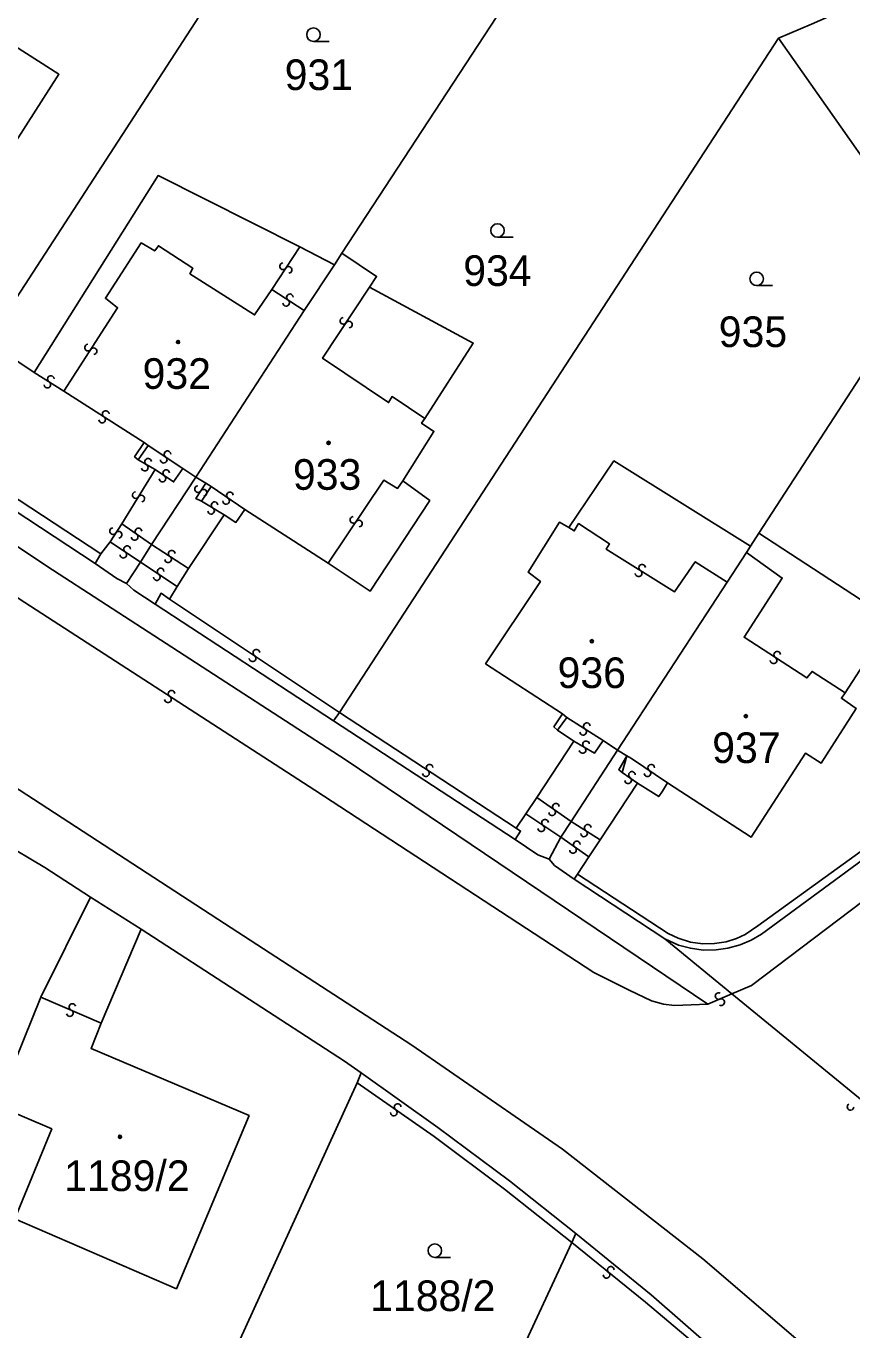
# Model space of a CAD drawing. Extents: x -600309 to -598967, y -1161267 to -1160292.
# Drawn here: x -600003.6 to -599957.8, y -1160420.2 to -1160347.8 of the extents above; entities that cross this region are included whole.
import ezdxf

# ---------------------------------------------------------------- set-up
doc = ezdxf.new("R2010")
doc.units = 0
for name, color, linetype in [('Level 1', 7, 'Continuous'), ('Level 13', 7, 'Continuous'), ('Level 3', 7, 'Continuous'), ('Level 4', 7, 'Continuous'), ('Level 5', 7, 'Continuous'), ('Level 60', 7, 'Continuous'), ('Vrstva 60', 7, 'Continuous')]:
    doc.layers.add(name, color=color, linetype=linetype)

msp = doc.modelspace()

# ---------------------------------------------------------------- linework, layer by layer
at = {"layer": 'Level 1'}
for points in [[(-599985.02, -1160333.4), (-600005.73, -1160365.35)], [(-599973.4, -1160341.02), (-599986.11, -1160360.44)], [(-600013.04, -1160343.31), (-600001.8, -1160350.51), (-600009.56, -1160362.64), (-600010.82, -1160361.78), (-600013.59, -1160366.12)], [(-599960.06, -1160347.74), (-599961.88, -1160348.52)], [(-599961.88, -1160348.52), (-599986.23, -1160385.92)], [(-599961.88, -1160348.52), (-599953.18, -1160360.9)], [(-599988.44, -1160360.09), (-599996.3, -1160356.14), (-600003.16, -1160367.07)], [(-599986.52, -1160361.09), (-599988.44, -1160360.09)], [(-599986.11, -1160360.44), (-599986.52, -1160361.09)], [(-599986.11, -1160360.44), (-599984.18, -1160361.73), (-599984.57, -1160362.32)], [(-599986.52, -1160361.09), (-599988.2, -1160363.63)], [(-599953.18, -1160360.9), (-599962.98, -1160375.98)], [(-599984.57, -1160362.32), (-599978.82, -1160365.43), (-599981.51, -1160369.61)], [(-599988.2, -1160363.63), (-599994.2, -1160372.87)], [(-600003.16, -1160367.07), (-600005.73, -1160365.35)], [(-599981.51, -1160369.61), (-599981.68, -1160369.88), (-599981, -1160370.33), (-599982.73, -1160373.08)], [(-599999.78, -1160377.66), (-600009.6, -1160371.2)], [(-599963.44, -1160376.7), (-599971.02, -1160371.97), (-599973.51, -1160375.67)], [(-599994.2, -1160372.87), (-599996.66, -1160376.6)], [(-599982.73, -1160373.08), (-599981.23, -1160374.17), (-599984.54, -1160379.2), (-599986.86, -1160377.65)], [(-599992.64, -1160374.96), (-599994.61, -1160377.94)], [(-599991.48, -1160374.67), (-599991.98, -1160375.38), (-599992.64, -1160374.96)], [(-599986.86, -1160377.65), (-599991.48, -1160374.67)], [(-599973.51, -1160375.67), (-599974.04, -1160375.37), (-599975.78, -1160378.14), (-599975.09, -1160378.65), (-599978.13, -1160383.22), (-599973.86, -1160386)], [(-599962.98, -1160375.98), (-599963.44, -1160376.7)], [(-599962.98, -1160375.98), (-599955.58, -1160380.8), (-599958.2, -1160384.83)], [(-599996.66, -1160376.6), (-599997.28, -1160377.58)], [(-599963.67, -1160377.05), (-599964.74, -1160378.7)], [(-599963.44, -1160376.7), (-599963.67, -1160377.05)], [(-599998.05, -1160378.77), (-599998.58, -1160378.49), (-599999.78, -1160377.66)], [(-599997.28, -1160377.58), (-599998.05, -1160378.77)], [(-599994.61, -1160377.94), (-599995.23, -1160378.94)], [(-599996.45, -1160379.91), (-599997.65, -1160379.13), (-599998.05, -1160378.77)], [(-599995.67, -1160379.63), (-599996.13, -1160379.31), (-599996.45, -1160379.91)], [(-599995.23, -1160378.94), (-599995.67, -1160379.63)], [(-599964.74, -1160378.7), (-599970.81, -1160388.01)], [(-599986.57, -1160386.39), (-599996.45, -1160379.91)], [(-599941.94, -1160383.8), (-599947.99, -1160387.75), (-599955.91, -1160393.14), (-599962.84, -1160398.22), (-599963.41, -1160398.56), (-599964.02, -1160398.82), (-599964.69, -1160399.01), (-599965.35, -1160399.1), (-599966.07, -1160399.11), (-599966.77, -1160399.01), (-599967.44, -1160398.83), (-599968.2, -1160398.49)], [(-599958.2, -1160384.83), (-599958.4, -1160385.14), (-599957.58, -1160385.71), (-599959.52, -1160388.73), (-599960.4, -1160388.19), (-599963.41, -1160392.85), (-599968.05, -1160389.83)], [(-599986.23, -1160385.92), (-599986.57, -1160386.39)], [(-599976.5, -1160392.98), (-599986.57, -1160386.39)], [(-599973.86, -1160386), (-599974.34, -1160386.72), (-599974.14, -1160386.91)], [(-599974.14, -1160386.91), (-599973.23, -1160387.51)], [(-599973.23, -1160387.51), (-599975.3, -1160390.65)], [(-599970.81, -1160388.01), (-599973.38, -1160391.97)], [(-599969.7, -1160389.84), (-599971.77, -1160393)], [(-599968.05, -1160389.83), (-599968.32, -1160390.3), (-599968.53, -1160390.59), (-599969.7, -1160389.84)], [(-599975.3, -1160390.65), (-599975.91, -1160391.55)], [(-599975.91, -1160391.55), (-599976.44, -1160392.35)], [(-599976.44, -1160392.35), (-599976.19, -1160392.51), (-599976.5, -1160392.98)], [(-599973.38, -1160391.97), (-599973.96, -1160392.85)], [(-600005, -1160393.09), (-600002.57, -1160394.53), (-600000.04, -1160396.18)], [(-599974.61, -1160394.06), (-599975.24, -1160393.82), (-599976.5, -1160392.98)], [(-599973.96, -1160392.85), (-599974.61, -1160394.06)], [(-599971.77, -1160393), (-599972.4, -1160393.94)], [(-599973.22, -1160395.17), (-599974.31, -1160394.42), (-599974.61, -1160394.06)], [(-599972.4, -1160393.94), (-599973.03, -1160394.89)], [(-599973.03, -1160394.89), (-599973.22, -1160395.17)], [(-599968.2, -1160398.49), (-599973.22, -1160395.17)], [(-600000.04, -1160396.18), (-600002.79, -1160401.73)], [(-600000.04, -1160396.18), (-599997.23, -1160397.94)], [(-599999.45, -1160403.16), (-599997.23, -1160397.94)], [(-599997.23, -1160397.94), (-599985.95, -1160405.27), (-599985.04, -1160405.92)], [(-599968.2, -1160398.49), (-599964.48, -1160401.54)], [(-600002.79, -1160401.73), (-600005.24, -1160407.73), (-600002.19, -1160409.03), (-600004.24, -1160414.02), (-599995.28, -1160417.9), (-599991.25, -1160408.29), (-600000.01, -1160404.57), (-599999.45, -1160403.16)], [(-599964.48, -1160401.54), (-599957.66, -1160407.13)], [(-599985.25, -1160406.48), (-599985.04, -1160405.92)], [(-599985.04, -1160405.92), (-599980.78, -1160408.96), (-599976.81, -1160411.91), (-599973.13, -1160414.83)], [(-599993.87, -1160425.35), (-599985.25, -1160406.48)], [(-599973.13, -1160414.83), (-599973.35, -1160415.33)], [(-599973.13, -1160414.83), (-599968.95, -1160418.24), (-599965.44, -1160421.3), (-599961.56, -1160424.77)], [(-599973.35, -1160415.33), (-599978.05, -1160425.46)]]:
    msp.add_lwpolyline(points, dxfattribs=at)
at = {"layer": 'Level 13'}
for centre, start, end in [((-599989.364, -1160361.168), 94.35736, 326.45536), ((-599989.056, -1160361.371), 274.14291, 146.73291), ((-599988.987, -1160362.887), 4.05568, 236.15368), ((-599989.192, -1160363.193), 183.84123, 56.43123), ((-599986.023, -1160364.198), 93.80425, 326.39425), ((-599985.717, -1160364.403), 274.01871, 146.11671), ((-600000.184, -1160365.679), 94.54984, 326.64784), ((-599999.876, -1160365.88), 274.33539, 146.92539), ((-600002.438, -1160367.736), 185.27868, 57.86868), ((-600002.241, -1160367.424), 5.49314, 237.59113), ((-599999.2, -1160369.365), 4.52077, 237.11077), ((-599999.401, -1160369.674), 184.73523, 56.83322), ((-599995.777, -1160371.598), 3.32998, 235.91998), ((-599996.847, -1160372.02), 7.75792, 239.85592), ((-599995.984, -1160371.902), 183.54444, 55.64244), ((-599997.032, -1160372.34), 187.54347, 60.13347), ((-599996.053, -1160372.943), 183.46821, 56.05821), ((-599995.846, -1160372.637), 3.68267, 235.78066), ((-599994.085, -1160373.53), 94.55794, 327.14794), ((-599993.776, -1160373.731), 274.7724, 146.8704), ((-599997.536, -1160373.863), 95.58265, 328.17265), ((-599997.224, -1160374.058), 275.7971, 147.8951), ((-599993.162, -1160374.424), 5.86847, 237.96646), ((-599992.525, -1160374.181), 182.76695, 55.35695), ((-599992.314, -1160373.879), 2.98141, 235.0794), ((-599993.357, -1160374.737), 185.65401, 58.24401), ((-599998.794, -1160375.859), 94.13441, 326.72441), ((-599997.384, -1160375.879), 2.73179, 234.82978), ((-599985.463, -1160375.237), 93.38244, 325.97244), ((-599985.158, -1160375.444), 273.59689, 145.69489), ((-599998.486, -1160376.062), 274.34887, 146.44686), ((-599997.595, -1160376.181), 182.51733, 55.10733), ((-599998.223, -1160377.173), 183.46821, 56.05821), ((-599998.016, -1160376.867), 3.68267, 235.78066), ((-599995.538, -1160377.117), 4.20175, 236.29975), ((-599996.157, -1160378.107), 3.81186, 235.90985), ((-599995.741, -1160377.424), 183.9873, 56.5773), ((-599969.45, -1160377.895), 5.177, 237.275), ((-599996.362, -1160378.413), 183.5974, 56.1874), ((-599969.649, -1160378.205), 184.96254, 57.55254), ((-599991.053, -1160382.923), 183.48222, 56.07222), ((-599990.846, -1160382.617), 3.69668, 235.79467), ((-599962.161, -1160383.034), 184.23262, 56.82262), ((-599961.958, -1160382.726), 4.44708, 236.54507), ((-599995.752, -1160385.194), 184.45419, 56.55219), ((-599995.549, -1160384.886), 4.23974, 236.82974), ((-599972.519, -1160386.686), 4.75349, 236.85149), ((-599972.72, -1160386.995), 184.53904, 57.12904), ((-599972.756, -1160388.007), 186.12001, 58.71001), ((-599972.563, -1160387.693), 6.33447, 238.43247), ((-599981.442, -1160389.293), 183.86166, 56.45166), ((-599981.237, -1160388.987), 4.07612, 236.17412), ((-599970.013, -1160389.389), 2.60754, 234.70553), ((-599969.154, -1160389.302), 182.94258, 55.53258), ((-599968.945, -1160388.998), 3.15703, 235.25503), ((-599970.226, -1160389.691), 182.39308, 54.98308), ((-599974.445, -1160391.461), 182.64976, 55.23976), ((-599974.234, -1160391.159), 2.86421, 234.96221), ((-599975.043, -1160392.353), 183.46821, 56.05821), ((-599974.836, -1160392.047), 3.68267, 235.78066), ((-599972.469, -1160392.326), 4.76359, 236.86159), ((-599973.073, -1160393.25), 2.43004, 234.52804), ((-599972.67, -1160392.635), 184.54913, 57.13913), ((-599973.286, -1160393.55), 182.21559, 54.80559), ((-599965.212, -1160401.661), 60.35687, 292.94687), ((-599965.069, -1160402), 240.57133, 112.66932), ((-600001.193, -1160402.609), 193.98039, 66.57039), ((-600001.046, -1160402.271), 14.19485, 246.29285), ((-599983.226, -1160408.12), 182.18431, 54.77431), ((-599983.013, -1160407.82), 2.39877, 234.49677), ((-599957.894, -1160407.806), 122.98351, 355.57351), ((-599971.427, -1160417.132), 178.10674, 50.69674), ((-599971.192, -1160416.848), 358.32119, 230.41919)]:
    msp.add_arc(centre, 0.184, start, end, dxfattribs=at)
at = {"layer": 'Level 3'}
for points in [[(-600028.67, -1160360.31), (-600002.46, -1160377.81), (-599985.92, -1160388.53), (-599965.81, -1160402.11)], [(-600001.52, -1160368.09), (-599998.54, -1160363.47), (-599999.22, -1160362.94), (-599997.24, -1160359.87), (-599996.48, -1160360.32), (-599996.28, -1160360.03), (-599994.36, -1160361.28), (-599994.53, -1160361.58), (-599990.94, -1160363.87), (-599989.98, -1160362.46)], [(-599989.98, -1160362.46), (-599988.44, -1160360.09)], [(-599899.14, -1160360.13), (-599900.24, -1160362.89), (-599919.3, -1160372.78), (-599932.71, -1160380.45), (-599942.21, -1160386.33), (-599950.05, -1160391.5), (-599957.16, -1160396.36), (-599963.39, -1160401.08), (-599964.48, -1160401.54)], [(-599912.7, -1160482.51), (-599912.12, -1160481.96), (-599911.66, -1160481.24), (-599911.44, -1160480.44), (-599911.45, -1160479.4), (-599911.76, -1160478.46), (-599912.23, -1160477.79), (-599914.13, -1160474.8), (-599932.72, -1160449.47), (-599939, -1160442.13), (-599955.49, -1160425.33), (-599966.09, -1160416.24), (-599973.86, -1160410.16), (-599982.22, -1160404.39), (-599992.61, -1160397.63), (-600009.1, -1160386.91), (-600023.99, -1160377.27), (-600035.97, -1160369.05), (-600043.73, -1160362.3), (-600044.47, -1160362.08), (-600045.32, -1160361.98), (-600046.31, -1160362.05), (-600047.41, -1160362.36), (-600048.26, -1160362.83)], [(-599965.81, -1160402.11), (-599966.73, -1160402.15), (-599967.65, -1160402.19), (-599968.27, -1160402.11), (-599968.94, -1160401.92), (-599970.17, -1160401.33), (-599972.13, -1160400.36), (-599987.61, -1160390.24), (-600003.69, -1160379.83), (-600018.92, -1160369.76), (-600030, -1160362.06)], [(-599989.98, -1160362.46), (-599988.2, -1160363.63)], [(-599984.57, -1160362.32), (-599987.17, -1160366.27), (-599983.51, -1160368.73), (-599983.32, -1160368.4), (-599981.51, -1160369.61)], [(-600003.16, -1160367.07), (-600001.52, -1160368.09)], [(-599997.07, -1160370.94), (-600001.52, -1160368.09)], [(-600009.25, -1160370.71), (-599999.47, -1160377.12)], [(-599997.07, -1160370.94), (-599997.6, -1160371.74), (-599997.41, -1160371.91)], [(-599996.84, -1160371.11), (-599997.41, -1160371.91)], [(-599996.84, -1160371.11), (-599997.07, -1160370.94)], [(-599994.93, -1160372.39), (-599996.84, -1160371.11)], [(-599997.41, -1160371.91), (-599996.46, -1160372.45)], [(-599996.46, -1160372.45), (-599998.31, -1160375.46)], [(-599996.46, -1160372.45), (-599995.44, -1160373.13), (-599994.93, -1160372.39)], [(-599994.2, -1160372.87), (-599994.93, -1160372.39)], [(-599994.2, -1160372.87), (-599993.65, -1160373.2)], [(-599993.65, -1160373.2), (-599994.2, -1160374.06), (-599993.88, -1160374.2)], [(-599993.35, -1160373.39), (-599993.88, -1160374.2)], [(-599993.65, -1160373.2), (-599993.35, -1160373.39)], [(-599993.35, -1160373.39), (-599991.48, -1160374.67)], [(-599982.73, -1160373.08), (-599983.01, -1160373.49), (-599983.77, -1160373.03), (-599986.86, -1160377.65)], [(-599993.88, -1160374.2), (-599992.64, -1160374.96)], [(-599998.31, -1160375.46), (-599998.96, -1160376.46)], [(-599998.31, -1160375.46), (-599996.66, -1160376.6)], [(-599973.51, -1160375.67), (-599973.22, -1160375.85), (-599972.98, -1160375.44), (-599971.26, -1160376.57), (-599971.44, -1160376.86), (-599967.66, -1160379.24), (-599966.51, -1160377.56), (-599964.74, -1160378.7)], [(-599998.96, -1160376.46), (-599999.47, -1160377.12)], [(-599998.96, -1160376.46), (-599997.28, -1160377.58)], [(-599999.47, -1160377.12), (-599999.78, -1160377.66)], [(-599996.66, -1160376.6), (-599994.61, -1160377.94)], [(-599963.67, -1160377.05), (-599961.68, -1160378.47), (-599963.8, -1160381.75), (-599960.31, -1160384.01), (-599960.03, -1160383.65), (-599958.2, -1160384.83)], [(-599997.28, -1160377.58), (-599995.23, -1160378.94)], [(-599995.67, -1160379.63), (-599986.23, -1160385.92)], [(-599973.03, -1160394.89), (-599968, -1160398.19), (-599967.45, -1160398.45), (-599966.77, -1160398.67), (-599966.09, -1160398.76), (-599965.43, -1160398.75), (-599964.79, -1160398.65), (-599964.21, -1160398.47), (-599963.73, -1160398.24), (-599963.03, -1160397.77), (-599956.11, -1160392.76), (-599948.07, -1160387.31), (-599942.17, -1160383.43)], [(-599986.23, -1160385.92), (-599976.44, -1160392.35)], [(-599973.62, -1160386.2), (-599974.14, -1160386.91)], [(-599973.86, -1160386), (-599973.62, -1160386.2)], [(-599973.62, -1160386.2), (-599971.62, -1160387.48)], [(-599973.23, -1160387.51), (-599972.1, -1160388.19), (-599971.62, -1160387.48)], [(-599971.62, -1160387.48), (-599970.81, -1160388.01)], [(-599970.81, -1160388.01), (-599970.3, -1160388.33)], [(-599970.3, -1160388.33), (-599970.75, -1160389.1), (-599970.55, -1160389.25)], [(-599970.3, -1160388.33), (-599970.55, -1160389.25)], [(-599970.3, -1160388.33), (-599970.05, -1160388.47), (-599968.05, -1160389.83)], [(-599970.55, -1160389.25), (-599969.7, -1160389.84)], [(-599975.3, -1160390.65), (-599973.38, -1160391.97)], [(-599975.91, -1160391.55), (-599973.96, -1160392.85)], [(-599973.38, -1160391.97), (-599971.77, -1160393)], [(-599973.96, -1160392.85), (-599972.4, -1160393.94)], [(-600002.79, -1160401.73), (-599999.45, -1160403.16)], [(-599964.48, -1160401.54), (-599965.81, -1160402.11)], [(-599985.25, -1160406.48), (-599980.99, -1160409.46), (-599977.08, -1160412.38), (-599973.35, -1160415.33)], [(-599973.35, -1160415.33), (-599969.27, -1160418.64), (-599965.74, -1160421.63)]]:
    msp.add_lwpolyline(points, dxfattribs=at)
at = {"layer": 'Level 5'}
for p, q in [((-599987.68, -1160348.69), (-599986.805, -1160348.69)), ((-599977.47, -1160359.56), (-599976.595, -1160359.56)), ((-599963.1, -1160362.24), (-599962.225, -1160362.24)), ((-599980.95, -1160416.16), (-599980.075, -1160416.16))]:
    msp.add_line(p, q, dxfattribs=at)
for centre, radius in [((-599987.68, -1160348.315), 0.375), ((-599977.47, -1160359.185), 0.375), ((-599963.1, -1160361.865), 0.375), ((-599995.19, -1160365.37), 0.09), ((-599995.19, -1160365.37), 0.0521), ((-599986.84, -1160370.97), 0.09), ((-599986.84, -1160370.97), 0.0521), ((-599972.24, -1160381.97), 0.09), ((-599972.24, -1160381.97), 0.0521), ((-599963.7, -1160386.13), 0.09), ((-599963.7, -1160386.13), 0.0521), ((-599998.41, -1160409.47), 0.09), ((-599998.41, -1160409.47), 0.0521), ((-599980.95, -1160415.785), 0.375)]:
    msp.add_circle(centre, radius, dxfattribs=at)
at = {"layer": 'Level 60'}
for points in [[(-599997.83, -1160323.39), (-599985.02, -1160333.4), (-600005.73, -1160365.35), (-600009.25, -1160370.71), (-600009.6, -1160371.2), (-600014.68, -1160367.84), (-600014.42, -1160367.4), (-600014, -1160366.76), (-600013.59, -1160366.12), (-600010.82, -1160361.78), (-600009.56, -1160362.64), (-600001.8, -1160350.51), (-600013.04, -1160343.31), (-600010.6, -1160339.6), (-600008.56, -1160336.97), (-600007.66, -1160335.81), (-600004.11, -1160331.42), (-599998.3, -1160324.05)], [(-599985.02, -1160333.4), (-599973.4, -1160341.02), (-599986.11, -1160360.44), (-599986.52, -1160361.09), (-599988.44, -1160360.09), (-599996.3, -1160356.14), (-600003.16, -1160367.07), (-600005.73, -1160365.35)], [(-600014.85, -1160346.02), (-600013.04, -1160343.31), (-600001.8, -1160350.51), (-600009.56, -1160362.64), (-600010.82, -1160361.78), (-600013.59, -1160366.12), (-600014, -1160366.76), (-600014.42, -1160367.4), (-600014.68, -1160367.84), (-600024.83, -1160361.13), (-600024.51, -1160360.69), (-600021.03, -1160355.37)], [(-599986.23, -1160385.92), (-599961.88, -1160348.52), (-599953.18, -1160360.9), (-599962.98, -1160375.98), (-599963.44, -1160376.7), (-599971.02, -1160371.97), (-599973.51, -1160375.67), (-599974.04, -1160375.37), (-599975.78, -1160378.14), (-599975.09, -1160378.65), (-599978.13, -1160383.22), (-599973.86, -1160386), (-599974.34, -1160386.72), (-599974.14, -1160386.91), (-599973.23, -1160387.51), (-599975.3, -1160390.65), (-599975.91, -1160391.55), (-599976.44, -1160392.35), (-599976.19, -1160392.51), (-599976.5, -1160392.98), (-599986.57, -1160386.39)], [(-600009.25, -1160370.71), (-600005.73, -1160365.35), (-600003.16, -1160367.07), (-599996.3, -1160356.14), (-599988.44, -1160360.09), (-599986.52, -1160361.09), (-599988.2, -1160363.63), (-599994.2, -1160372.87), (-599996.66, -1160376.6), (-599997.28, -1160377.58), (-599998.05, -1160378.77), (-599998.58, -1160378.49), (-599999.78, -1160377.66), (-600009.6, -1160371.2)], [(-599986.52, -1160361.09), (-599986.11, -1160360.44), (-599984.18, -1160361.73), (-599984.57, -1160362.32), (-599978.82, -1160365.43), (-599981.51, -1160369.61), (-599981.68, -1160369.88), (-599981, -1160370.33), (-599982.73, -1160373.08), (-599981.23, -1160374.17), (-599984.54, -1160379.2), (-599986.86, -1160377.65), (-599991.48, -1160374.67), (-599991.98, -1160375.38), (-599992.64, -1160374.96), (-599994.61, -1160377.94), (-599995.23, -1160378.94), (-599995.67, -1160379.63), (-599996.13, -1160379.31), (-599996.45, -1160379.91), (-599997.65, -1160379.13), (-599998.05, -1160378.77), (-599997.28, -1160377.58), (-599996.66, -1160376.6), (-599994.2, -1160372.87), (-599988.2, -1160363.63)], [(-599971.02, -1160371.97), (-599963.44, -1160376.7), (-599963.67, -1160377.05), (-599964.74, -1160378.7), (-599970.81, -1160388.01), (-599973.38, -1160391.97), (-599973.96, -1160392.85), (-599974.61, -1160394.06), (-599975.24, -1160393.82), (-599976.5, -1160392.98), (-599976.19, -1160392.51), (-599976.44, -1160392.35), (-599975.91, -1160391.55), (-599975.3, -1160390.65), (-599973.23, -1160387.51), (-599974.14, -1160386.91), (-599974.34, -1160386.72), (-599973.86, -1160386), (-599978.13, -1160383.22), (-599975.09, -1160378.65), (-599975.78, -1160378.14), (-599974.04, -1160375.37), (-599973.51, -1160375.67)], [(-599963.44, -1160376.7), (-599962.98, -1160375.98), (-599955.58, -1160380.8), (-599958.2, -1160384.83), (-599958.4, -1160385.14), (-599957.58, -1160385.71), (-599959.52, -1160388.73), (-599960.4, -1160388.19), (-599963.41, -1160392.85), (-599968.05, -1160389.83), (-599968.32, -1160390.3), (-599968.53, -1160390.59), (-599969.7, -1160389.84), (-599971.77, -1160393), (-599972.4, -1160393.94), (-599973.03, -1160394.89), (-599973.22, -1160395.17), (-599974.31, -1160394.42), (-599974.61, -1160394.06), (-599973.96, -1160392.85), (-599973.38, -1160391.97), (-599970.81, -1160388.01), (-599964.74, -1160378.7), (-599963.67, -1160377.05)], [(-599998.05, -1160434.45), (-600007.2, -1160454.31), (-600028.59, -1160444.1), (-600023.36, -1160432.59), (-600005.13, -1160393.36), (-600005, -1160393.09), (-600002.57, -1160394.53), (-600000.04, -1160396.18), (-600002.79, -1160401.73), (-600005.24, -1160407.73), (-600002.19, -1160409.03), (-600004.24, -1160414.02), (-599995.28, -1160417.9), (-599991.25, -1160408.29), (-600000.01, -1160404.57), (-599999.45, -1160403.16), (-599997.23, -1160397.94), (-599985.95, -1160405.27), (-599985.04, -1160405.92), (-599985.25, -1160406.48), (-599993.87, -1160425.35), (-599996.65, -1160431.31)], [(-600002.79, -1160401.73), (-600000.04, -1160396.18), (-599997.23, -1160397.94), (-599999.45, -1160403.16), (-600000.01, -1160404.57), (-599991.25, -1160408.29), (-599995.28, -1160417.9), (-600004.24, -1160414.02), (-600002.19, -1160409.03), (-600005.24, -1160407.73)], [(-599990.52, -1160437.93), (-599998.05, -1160434.45), (-599996.65, -1160431.31), (-599993.87, -1160425.35), (-599985.25, -1160406.48), (-599985.04, -1160405.92), (-599980.78, -1160408.96), (-599976.81, -1160411.91), (-599973.13, -1160414.83), (-599973.35, -1160415.33), (-599978.05, -1160425.46), (-599987.94, -1160420.76), (-599990.74, -1160426.81), (-599987.69, -1160428.35), (-599989.54, -1160432.4), (-599988.2, -1160433.06)], [(-599961.8, -1160425.34), (-599964.72, -1160431.81), (-599967.32, -1160430.58), (-599978.05, -1160425.46), (-599973.35, -1160415.33), (-599973.13, -1160414.83), (-599968.95, -1160418.24), (-599965.44, -1160421.3), (-599961.56, -1160424.77)]]:
    msp.add_lwpolyline(points, close=True, dxfattribs=at)
for points in [[(-599953.18, -1160360.9), (-599961.88, -1160348.52), (-599960.06, -1160347.74), (-599941.37, -1160339.49)], [(-599960.06, -1160347.74), (-599961.88, -1160348.52), (-599986.23, -1160385.92), (-599986.57, -1160386.39), (-599996.45, -1160379.91), (-599996.13, -1160379.31), (-599995.67, -1160379.63), (-599995.23, -1160378.94), (-599994.61, -1160377.94), (-599992.64, -1160374.96), (-599991.98, -1160375.38), (-599991.48, -1160374.67), (-599986.86, -1160377.65), (-599984.54, -1160379.2), (-599981.23, -1160374.17), (-599982.73, -1160373.08), (-599981, -1160370.33), (-599981.68, -1160369.88), (-599981.51, -1160369.61), (-599978.82, -1160365.43), (-599984.57, -1160362.32), (-599984.18, -1160361.73), (-599986.11, -1160360.44), (-599973.4, -1160341.02)], [(-599955.91, -1160393.14), (-599962.84, -1160398.22), (-599963.41, -1160398.56), (-599964.02, -1160398.82), (-599964.69, -1160399.01), (-599965.35, -1160399.1), (-599966.07, -1160399.11), (-599966.77, -1160399.01), (-599967.44, -1160398.83), (-599968.2, -1160398.49), (-599973.22, -1160395.17), (-599973.03, -1160394.89), (-599972.4, -1160393.94), (-599971.77, -1160393), (-599969.7, -1160389.84), (-599968.53, -1160390.59), (-599968.32, -1160390.3), (-599968.05, -1160389.83), (-599963.41, -1160392.85), (-599960.4, -1160388.19), (-599959.52, -1160388.73), (-599957.58, -1160385.71), (-599958.4, -1160385.14), (-599958.2, -1160384.83), (-599955.58, -1160380.8), (-599962.98, -1160375.98), (-599953.18, -1160360.9)], [(-599957.66, -1160407.13), (-599964.48, -1160401.54), (-599968.2, -1160398.49), (-599967.44, -1160398.83), (-599966.77, -1160399.01), (-599966.07, -1160399.11), (-599965.35, -1160399.1), (-599964.69, -1160399.01), (-599964.02, -1160398.82), (-599963.41, -1160398.56), (-599962.84, -1160398.22), (-599955.91, -1160393.14)]]:
    msp.add_lwpolyline(points, dxfattribs=at)
at = {"layer": 'Vrstva 60'}
for points in [[(-599939.68, -1160423.47), (-599944.15, -1160419.18), (-599945.76, -1160417.71), (-599952.98, -1160410.97), (-599957.66, -1160407.13), (-599964.48, -1160401.54), (-599968.2, -1160398.49), (-599973.22, -1160395.17), (-599974.31, -1160394.42), (-599974.61, -1160394.06), (-599975.24, -1160393.82), (-599976.5, -1160392.98), (-599986.57, -1160386.39), (-599996.45, -1160379.91), (-599997.65, -1160379.13), (-599998.05, -1160378.77), (-599998.58, -1160378.49), (-599999.78, -1160377.66), (-600009.6, -1160371.2), (-600014.68, -1160367.84), (-600024.83, -1160361.13), (-600028.95, -1160358.16), (-600033.46, -1160354.46), (-600034.49, -1160353.45)], [(-600035.02, -1160372.69), (-600029.73, -1160376.63), (-600024.62, -1160380.27), (-600013.97, -1160387.13), (-600005, -1160393.09), (-600002.57, -1160394.53), (-600000.04, -1160396.18), (-599997.23, -1160397.94), (-599985.95, -1160405.27), (-599985.04, -1160405.92), (-599980.78, -1160408.96), (-599976.81, -1160411.91), (-599973.13, -1160414.83), (-599968.95, -1160418.24), (-599965.44, -1160421.3)]]:
    msp.add_lwpolyline(points, dxfattribs=at)

# ---------------------------------------------------------------- texts
at = {"layer": 'Level 4'}
for s, p in [('931', (-599989.274, -1160351.39)), ('934', (-599979.371, -1160362.26)), ('935', (-599965.202, -1160365.65)), ('932', (-599997.156, -1160367.97)), ('933', (-599988.818, -1160373.57)), ('936', (-599974.141, -1160384.57)), ('937', (-599965.566, -1160388.73)), ('1189/2', (-600001.502, -1160412.48)), ('1188/2', (-599984.535, -1160419.14))]:
    msp.add_text(s, height=1.7, dxfattribs=at).set_placement(p)

doc.saveas('drawing.dxf')
